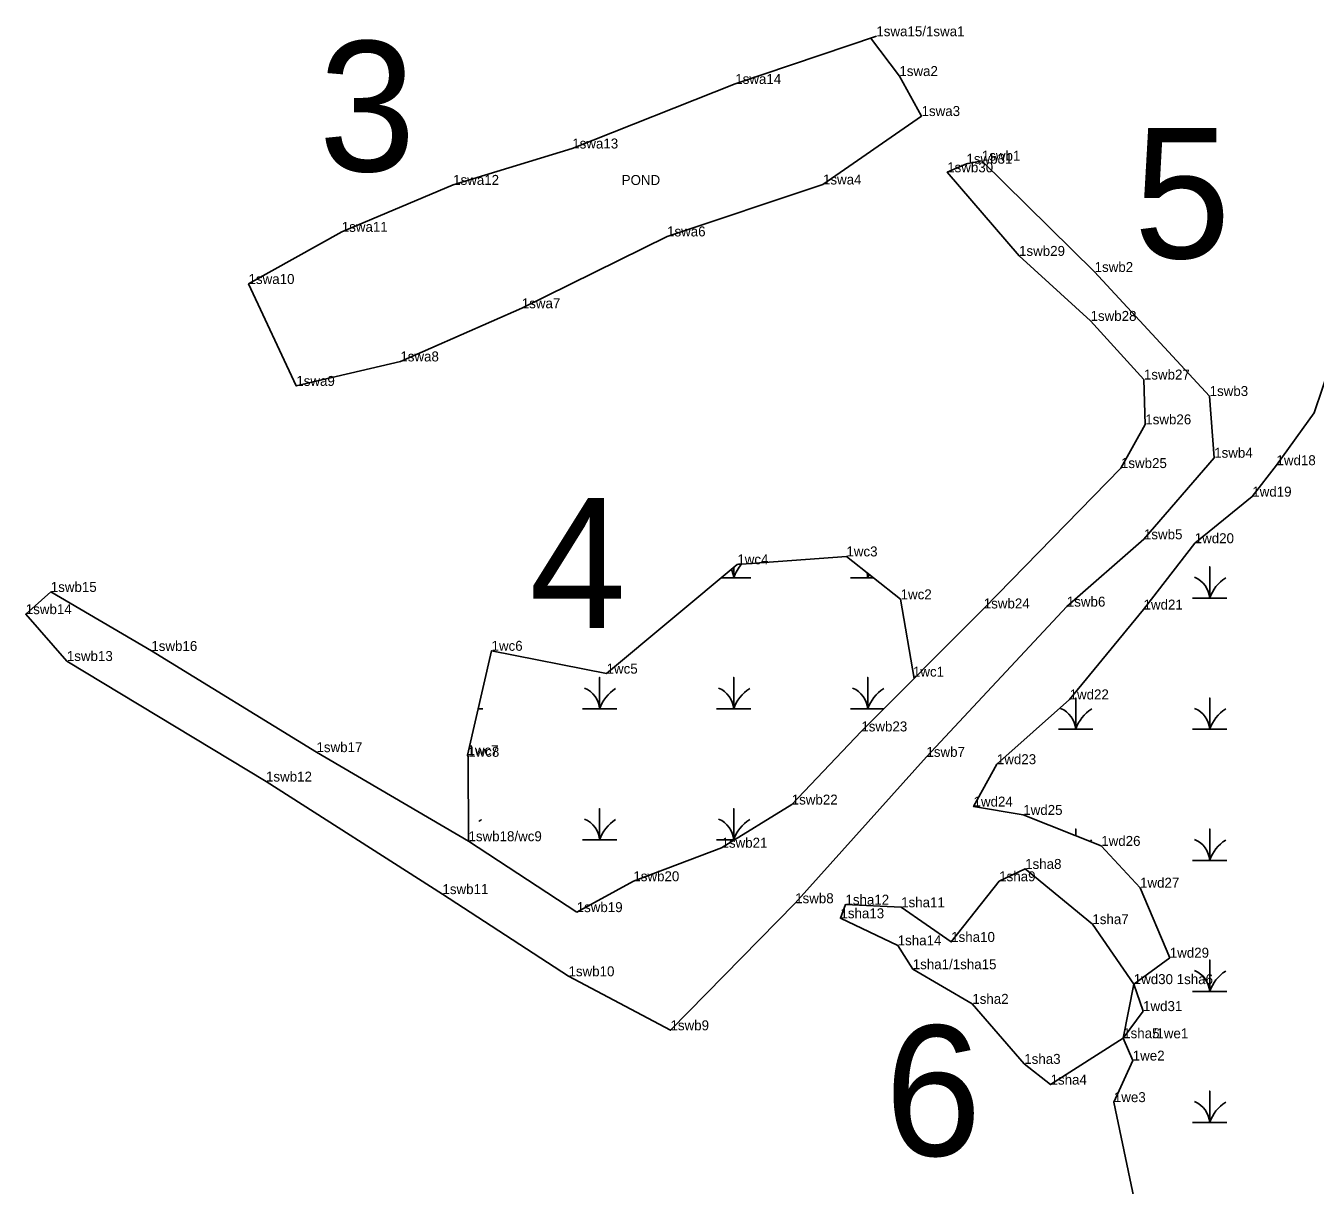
# Model space of a CAD drawing. Extents: x 2072529 to 2268796, y 436423 to 470406.
# Drawn here: x 2075517 to 2076164, y 466904 to 467486 of the extents above; entities that cross this region are included whole.
import ezdxf

# ---------------------------------------------------------------- set-up
doc = ezdxf.new("R2010")
doc.units = 0
for name, color, linetype in [('Default', 7, 'Continuous'), ('Exist Environmental Wetland Boundary', 7, 'Continuous'), ('Exist Environmental Wetland Boundary Cogo Comment', 7, 'Continuous'), ('Exist Hydro Jurisdictional Stream or Body of Water NEU Mitigable', 7, 'Continuous'), ('Exist Hydro Jurisdictional Stream or Body of Water NEU Mitigable Cogo Comment', 7, 'Continuous'), ('Exist Hydro Swamp or Marsh', 7, 'Continuous'), ('Old_Level_20', 7, 'Continuous')]:
    doc.layers.add(name, color=color, linetype=linetype)

msp = doc.modelspace()

# ---------------------------------------------------------------- linework, layer by layer
at = {"layer": 'Exist Environmental Wetland Boundary'}
for points in [[(2076077.38, 466875.89), (2076062.92, 466945.41), (2076072.38, 466966.27), (2076067.59, 466977.5), (2076077.56, 466991.11), (2076072.88, 467004.65), (2076090.97, 467017.9), (2076076.04, 467053.05), (2076056.58, 467074.03), (2076017.46, 467089.59), (2075992.51, 467093.79), (2076004.21, 467115.06), (2076040.7, 467147.55), (2076077.8, 467192.67), (2076103.48, 467225.98), (2076132.37, 467249.38), (2076144.51, 467265.15), (2076163.46, 467291.5), (2076171.77, 467316.2)], [(2075962.67, 467158.09), (2075955.92, 467197.81), (2075928.72, 467219.35), (2075873.98, 467215.36), (2075808.39, 467160.51), (2075750.66, 467171.96), (2075738.55, 467119.55), (2075738.95, 467118.77), (2075739.09, 467076.38)]]:
    msp.add_lwpolyline(points, dxfattribs=at)
at = {"layer": 'Exist Hydro Jurisdictional Stream or Body of Water NEU Mitigable'}
for points in [[(2075704.91, 467317.24), (2075652.7, 467304.94), (2075628.73, 467356.12), (2075675.51, 467382.29), (2075731.38, 467405.86), (2075791.16, 467424.12), (2075872.96, 467456.52), (2075943.75, 467480.46)], [(2075940.84, 467479.63), (2075955.3, 467460.49), (2075966.43, 467440.41), (2075916.96, 467406.06), (2075838.72, 467379.99), (2075765.83, 467343.91), (2075704.91, 467317.24)], [(2075793.46, 467040.83), (2075821.82, 467056.29), (2075866.06, 467073.12), (2075901.28, 467094.78), (2075936.2, 467131.49), (2075997.64, 467193.23), (2076066.47, 467263.7), (2076078.69, 467285.64), (2076077.99, 467308.14), (2076051.22, 467337.58), (2076015.34, 467370.21), (2075979.3, 467412.16), (2075988.96, 467416.48), (2075996.67, 467418), (2076053.26, 467362.14), (2076110.97, 467299.87), (2076113.26, 467268.89), (2076078.01, 467227.93), (2076039.32, 467194.15), (2075968.87, 467118.73), (2075903, 467045.26), (2075840.46, 466981.47), (2075789.27, 467008.59), (2075789.28, 467008.62)], [(2075789.27, 467008.59), (2075726.03, 467049.84), (2075637.5, 467106.33), (2075537.57, 467166.85), (2075516.96, 467190.37), (2075529.5, 467201.53), (2075579.96, 467171.88), (2075662.83, 467121.1), (2075739.09, 467076.38), (2075793.39, 467040.79)]]:
    msp.add_lwpolyline(points, dxfattribs=at)
msp.add_lwpolyline([(2075962, 467012.12), (2075991.89, 466994.75), (2076017.97, 466964.61), (2076031.15, 466954.21), (2076067.59, 466977.5), (2076072.88, 467004.65), (2076052.14, 467034.76), (2076018.41, 467062.48), (2076005.39, 467056.26), (2075981.3, 467025.83), (2075956.19, 467043.22), (2075928.23, 467044.54), (2075925.72, 467037.71), (2075954.45, 467024.12)], close=True, dxfattribs=at)
at = {"layer": 'Exist Hydro Swamp or Marsh'}
for points in [[(2075865.89, 467208.6), (2075872.15, 467208.6), (2075872.15, 467213.84)], [(2075872.15, 467213.84), (2075872.15, 467208.6), (2075880.75, 467208.6)], [(2076102.41, 467198.37), (2076111.01, 467198.37), (2076111.01, 467214.16), (2076111.01, 467198.37), (2076119.61, 467198.37)], [(2075930.8, 467208.6), (2075939.4, 467208.6), (2075939.4, 467210.89)], [(2075939.4, 467210.89), (2075939.4, 467208.6), (2075942.3, 467208.6)], [(2075796.3, 467142.8), (2075804.9, 467142.8), (2075804.9, 467158.58), (2075804.9, 467142.8), (2075813.5, 467142.8)], [(2075863.55, 467142.8), (2075872.15, 467142.8), (2075872.15, 467158.58), (2075872.15, 467142.8), (2075880.75, 467142.8)], [(2075930.8, 467142.8), (2075939.4, 467142.8), (2075939.4, 467158.58), (2075939.4, 467142.8), (2075947.45, 467142.8)], [(2076035.16, 467132.57), (2076043.76, 467132.57), (2076043.76, 467148.36), (2076043.76, 467132.57), (2076052.36, 467132.57)], [(2076102.41, 467132.57), (2076111.01, 467132.57), (2076111.01, 467148.36), (2076111.01, 467132.57), (2076119.61, 467132.57)], [(2075743.93, 467142.8), (2075746.25, 467142.8)], [(2075796.3, 467077), (2075804.9, 467077), (2075804.9, 467092.78), (2075804.9, 467077), (2075813.5, 467077)], [(2075863.55, 467077), (2075872.15, 467077), (2075872.15, 467092.78), (2075872.15, 467077), (2075872.37, 467077)], [(2076043.76, 467079.13), (2076043.76, 467082.56), (2076043.76, 467079.13)], [(2076102.41, 467066.77), (2076111.01, 467066.77), (2076111.01, 467082.56), (2076111.01, 467066.77), (2076119.61, 467066.77)], [(2076102.41, 467000.97), (2076111.01, 467000.97), (2076111.01, 467016.76), (2076111.01, 467000.97), (2076119.61, 467000.97)], [(2076102.41, 466935.17), (2076111.01, 466935.17), (2076111.01, 466950.96), (2076111.01, 466935.17), (2076119.61, 466935.17)]]:
    msp.add_lwpolyline(points, dxfattribs=at)
for centre, radius, start, end in [((2075859.89, 467207.71), 12.3, 4.14034, 24.98693), ((2075890.4, 467202.54), 19.22, 137.47916, 161.62219), ((2075927.14, 467207.71), 12.3, 4.14034, 16.90239), ((2075957.65, 467202.54), 19.22, 156.01355, 161.62219), ((2076098.75, 467197.49), 12.3, 4.14034, 67.53497), ((2076129.26, 467192.31), 19.22, 122.12745, 161.62219), ((2075792.64, 467141.91), 12.3, 4.14034, 67.53497), ((2075823.15, 467136.74), 19.22, 122.12745, 161.62219), ((2075859.89, 467141.91), 12.3, 4.14034, 67.53497), ((2075890.4, 467136.74), 19.22, 122.12745, 161.62219), ((2075927.14, 467141.91), 12.3, 4.14034, 67.53497), ((2075957.65, 467136.74), 19.22, 122.12745, 161.62219), ((2076031.5, 467131.69), 12.3, 4.14034, 67.53497), ((2076062.01, 467126.51), 19.22, 122.12745, 161.62219), ((2076098.75, 467131.69), 12.3, 4.14034, 67.53497), ((2076129.26, 467126.51), 19.22, 122.12745, 161.62219), ((2075755.9, 467070.94), 19.22, 122.12745, 126.84294), ((2075792.64, 467076.11), 12.3, 4.14034, 67.53497), ((2075823.15, 467070.94), 19.22, 122.12745, 161.62219), ((2075859.89, 467076.11), 12.3, 4.14034, 67.53497), ((2075890.4, 467070.94), 19.22, 122.12745, 161.62219), ((2076062.01, 467060.71), 19.22, 122.12745, 125.67396), ((2076098.75, 467065.89), 12.3, 4.14034, 67.53497), ((2076129.26, 467060.71), 19.22, 122.12745, 161.62219), ((2076098.75, 467000.09), 12.3, 4.14034, 67.53497), ((2076129.26, 466994.91), 19.22, 122.12745, 161.62219), ((2076098.75, 466934.29), 12.3, 4.14034, 67.53497), ((2076129.26, 466929.11), 19.22, 122.12745, 161.62219)]:
    msp.add_arc(centre, radius, start, end, dxfattribs=at)
at = {"layer": 'Old_Level_20'}
for p, q in [((2075940.84, 467479.63), (2075940.84, 467479.63)), ((2075955.3, 467460.49), (2075955.3, 467460.49)), ((2075872.96, 467456.52), (2075872.96, 467456.52)), ((2075966.43, 467440.41), (2075966.43, 467440.41)), ((2075791.16, 467424.12), (2075791.16, 467424.12)), ((2075988.96, 467416.48), (2075988.96, 467416.48)), ((2075996.67, 467418), (2075996.67, 467418)), ((2075731.38, 467405.86), (2075731.38, 467405.86)), ((2075916.96, 467406.06), (2075916.96, 467406.06)), ((2075979.3, 467412.16), (2075979.3, 467412.16)), ((2075675.51, 467382.29), (2075675.51, 467382.29)), ((2075838.72, 467379.99), (2075838.72, 467379.99)), ((2076015.34, 467370.21), (2076015.34, 467370.21)), ((2076053.26, 467362.14), (2076053.26, 467362.14)), ((2075628.73, 467356.12), (2075628.73, 467356.12)), ((2075765.83, 467343.91), (2075765.83, 467343.91)), ((2076051.22, 467337.58), (2076051.22, 467337.58)), ((2075704.91, 467317.24), (2075704.91, 467317.24)), ((2075652.7, 467304.94), (2075652.7, 467304.94)), ((2076077.99, 467308.14), (2076077.99, 467308.14)), ((2076110.97, 467299.87), (2076110.97, 467299.87)), ((2076163.46, 467291.5), (2076163.46, 467291.5)), ((2076078.69, 467285.64), (2076078.69, 467285.64)), ((2076066.47, 467263.7), (2076066.47, 467263.7)), ((2076113.26, 467268.89), (2076113.26, 467268.89)), ((2076144.51, 467265.15), (2076144.51, 467265.15)), ((2076132.37, 467249.38), (2076132.37, 467249.38)), ((2076078.01, 467227.93), (2076078.01, 467227.93)), ((2076103.48, 467225.98), (2076103.48, 467225.98)), ((2075928.72, 467219.35), (2075928.72, 467219.35)), ((2075873.98, 467215.36), (2075873.98, 467215.36)), ((2075529.5, 467201.53), (2075529.5, 467201.53)), ((2075955.92, 467197.81), (2075955.92, 467197.81)), ((2075997.64, 467193.23), (2075997.64, 467193.23)), ((2076039.32, 467194.15), (2076039.32, 467194.15)), ((2076077.8, 467192.67), (2076077.8, 467192.67)), ((2075516.96, 467190.37), (2075516.96, 467190.37)), ((2075537.57, 467166.85), (2075537.57, 467166.85)), ((2075579.96, 467171.88), (2075579.96, 467171.88)), ((2075750.66, 467171.96), (2075750.66, 467171.96)), ((2075808.39, 467160.51), (2075808.39, 467160.51)), ((2075962.51, 467159.01), (2075962.51, 467159.01)), ((2076040.7, 467147.55), (2076040.7, 467147.55)), ((2075936.2, 467131.49), (2075936.2, 467131.49)), ((2075662.83, 467121.1), (2075662.83, 467121.1)), ((2075738.55, 467119.55), (2075738.55, 467119.55)), ((2075738.95, 467118.77), (2075738.95, 467118.77)), ((2075968.87, 467118.73), (2075968.87, 467118.73)), ((2076004.21, 467115.06), (2076004.21, 467115.06)), ((2075637.5, 467106.33), (2075637.5, 467106.33)), ((2075901.28, 467094.78), (2075901.28, 467094.78)), ((2075992.51, 467093.79), (2075992.51, 467093.79)), ((2076017.46, 467089.59), (2076017.46, 467089.59)), ((2075739.09, 467076.38), (2075739.09, 467076.38)), ((2075739.09, 467076.38), (2075739.09, 467076.38)), ((2075866.06, 467073.12), (2075866.06, 467073.12)), ((2076056.58, 467074.03), (2076056.58, 467074.03)), ((2076018.41, 467062.48), (2076018.41, 467062.48)), ((2075821.82, 467056.29), (2075821.82, 467056.29)), ((2076005.39, 467056.26), (2076005.39, 467056.26)), ((2076076.04, 467053.05), (2076076.04, 467053.05)), ((2075726.03, 467049.84), (2075726.03, 467049.84)), ((2075903, 467045.26), (2075903, 467045.26)), ((2075928.23, 467044.54), (2075928.23, 467044.54)), ((2075793.39, 467040.79), (2075793.39, 467040.79)), ((2075925.72, 467037.71), (2075925.72, 467037.71)), ((2075956.19, 467043.22), (2075956.19, 467043.22)), ((2076052.14, 467034.76), (2076052.14, 467034.76)), ((2075954.45, 467024.12), (2075954.45, 467024.12)), ((2075981.3, 467025.83), (2075981.3, 467025.83)), ((2076090.97, 467017.9), (2076090.97, 467017.9)), ((2075962, 467012.12), (2075962, 467012.12)), ((2075789.27, 467008.59), (2075789.27, 467008.59)), ((2075789.27, 467008.59), (2075789.27, 467008.59)), ((2076072.65, 467004.96), (2076072.65, 467004.96)), ((2076072.88, 467004.65), (2076072.88, 467004.65)), ((2075991.89, 466994.75), (2075991.89, 466994.75)), ((2076077.56, 466991.11), (2076077.56, 466991.11)), ((2075840.46, 466981.47), (2075840.46, 466981.47)), ((2076067.59, 466977.5), (2076067.59, 466977.5)), ((2076067.75, 466977.44), (2076067.75, 466977.44)), ((2076072.38, 466966.27), (2076072.38, 466966.27)), ((2076017.97, 466964.61), (2076017.97, 466964.61)), ((2076031.15, 466954.21), (2076031.15, 466954.21)), ((2076062.92, 466945.41), (2076062.92, 466945.41))]:
    msp.add_line(p, q, dxfattribs=at)

# ---------------------------------------------------------------- texts
at = {"layer": 'Default'}
for s, p in [('3', (2075663.96, 467412.68)), ('5', (2076072.88, 467369.04)), ('4', (2075769.56, 467183.34)), ('6', (2075947.92, 466918.5))]:
    msp.add_text(s, height=65.34, dxfattribs=at).set_placement(p)
at = {"layer": 'Exist Environmental Wetland Boundary Cogo Comment'}
for s, p in [('1wd18', (2076144.51, 467265.15)), ('1wd19', (2076132.37, 467249.38)), ('1wd20', (2076103.48, 467225.98)), ('1wc4', (2075873.98, 467215.36)), ('1wc3', (2075928.72, 467219.35)), ('1wc2', (2075955.92, 467197.81)), ('1wd21', (2076077.8, 467192.67)), ('1wc6', (2075750.66, 467171.96)), ('1wc5', (2075808.39, 467160.51)), ('1wc1', (2075962.1, 467159.01)), ('1wd22', (2076040.7, 467147.55)), ('1wc7', (2075738.55, 467119.55)), ('1wc8', (2075738.95, 467118.77)), ('1wd23', (2076004.21, 467115.06)), ('1wd24', (2075992.51, 467093.79)), ('1wd25', (2076017.46, 467089.59)), ('1swb18/wc9', (2075739.09, 467076.38)), ('1wd26', (2076056.58, 467074.03)), ('1wd27', (2076076.04, 467053.05)), ('1wd29', (2076090.97, 467017.9)), ('1wd30 1sha6', (2076072.88, 467004.65)), ('1wd31', (2076077.56, 466991.11)), ('1sha5', (2076067.59, 466977.5)), ('/1we1', (2076082.4, 466977.44)), ('1we2', (2076072.38, 466966.27)), ('1we3', (2076062.92, 466945.41))]:
    msp.add_text(s, height=5, dxfattribs=at).set_placement(p)
at = {"layer": 'Exist Hydro Jurisdictional Stream or Body of Water NEU Mitigable Cogo Comment'}
for s, p in [('1swa15/1swa1', (2075943.75, 467480.46)), ('1swa2', (2075955.3, 467460.49)), ('1swa14', (2075872.96, 467456.52)), ('1swa3', (2075966.43, 467440.41)), ('1swa13', (2075791.16, 467424.12)), ('1swb31', (2075988.96, 467416.48)), ('1swb1', (2075996.67, 467418)), ('1swb30', (2075979.3, 467412.16)), ('1swa12', (2075731.38, 467405.86)), ('POND', (2075815.96, 467405.8)), ('1swa4', (2075916.96, 467406.06)), ('1swa11', (2075675.51, 467382.29)), ('1swa6', (2075838.72, 467379.99)), ('1swb29', (2076015.34, 467370.21)), ('1swb2', (2076053.26, 467362.14)), ('1swa10', (2075628.73, 467356.12)), ('1swa7', (2075765.83, 467343.91)), ('1swb28', (2076051.22, 467337.58)), ('1swa8', (2075704.91, 467317.24)), ('1swa9', (2075652.7, 467304.94)), ('1swb27', (2076077.99, 467308.14)), ('1swb3', (2076110.97, 467299.87)), ('1swb26', (2076078.69, 467285.64)), ('1swb4', (2076113.26, 467268.89)), ('1swb25', (2076066.47, 467263.7)), ('1swb5', (2076078.01, 467227.93)), ('1swb15', (2075529.5, 467201.53)), ('1swb6', (2076039.32, 467194.15)), ('1swb14', (2075516.96, 467190.37)), ('1swb24', (2075997.64, 467193.23)), ('1swb16', (2075579.96, 467171.88)), ('1swb13', (2075537.57, 467166.85)), ('1swb23', (2075936.2, 467131.49)), ('1swb17', (2075662.83, 467121.1)), ('1swb7', (2075968.87, 467118.73)), ('1swb12', (2075637.5, 467106.33)), ('1swb22', (2075901.28, 467094.78)), ('1swb18', (2075739.09, 467076.38)), ('1swb21', (2075866.06, 467073.12)), ('1sha8', (2076018.41, 467062.48)), ('1swb20', (2075821.82, 467056.29)), ('1sha9', (2076005.39, 467056.26)), ('1swb11', (2075726.03, 467049.84)), ('1swb8', (2075903, 467045.26)), ('1swb19', (2075793.39, 467040.79)), ('1sha12', (2075928.23, 467044.54)), ('1sha11', (2075956.19, 467043.22)), ('1sha13', (2075925.72, 467037.71)), ('1sha7', (2076052.14, 467034.76)), ('1sha10', (2075981.3, 467025.83)), ('1sha14', (2075954.45, 467024.12)), ('1swb10', (2075789.27, 467008.59)), ('1sha1/1sha15', (2075962, 467012.12)), ('1sha2', (2075991.89, 466994.75)), ('1swb9', (2075840.46, 466981.47)), ('1sha3', (2076017.97, 466964.61)), ('1sha4', (2076031.15, 466954.21))]:
    msp.add_text(s, height=5, dxfattribs=at).set_placement(p)

doc.saveas('drawing.dxf')
